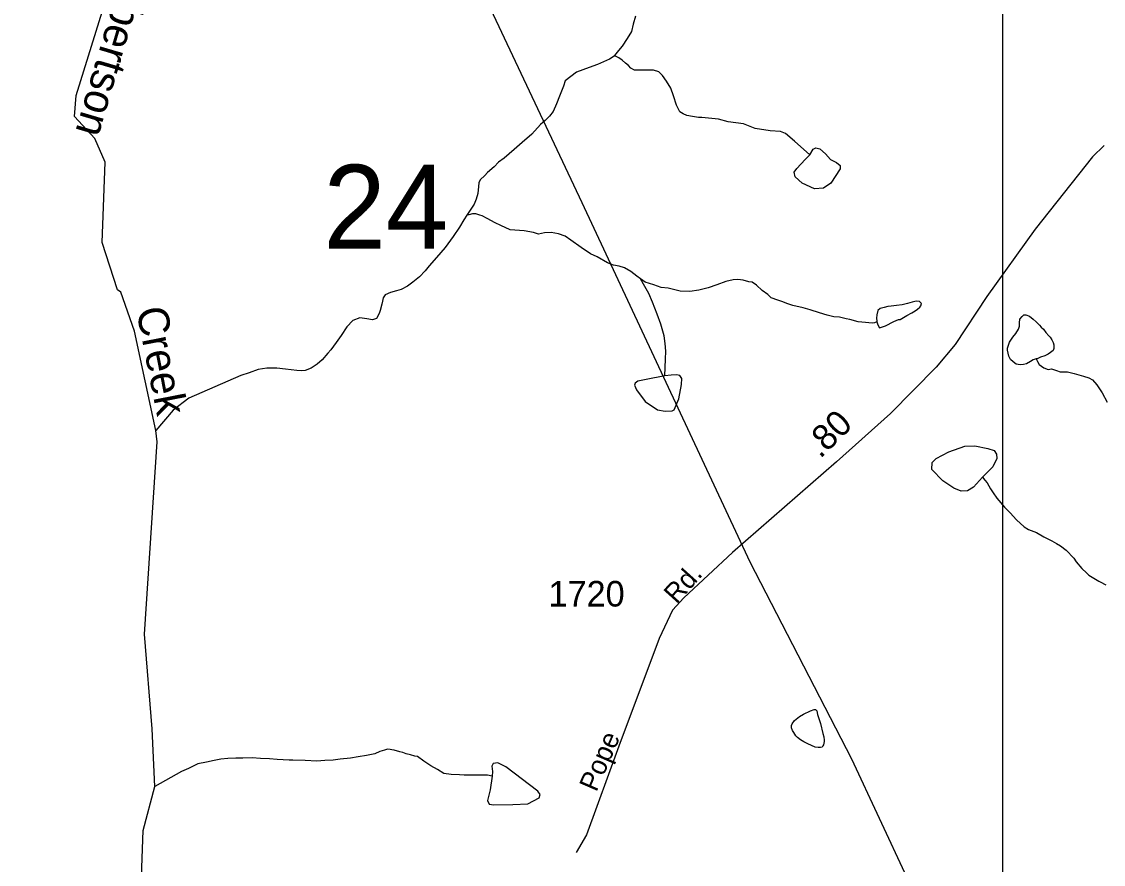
# Model space of a CAD drawing. Extents: x 2056842 to 2160602, y 826753 to 1016856.
# Drawn here: x 2099244 to 2104528, y 850429 to 854545 of the extents above; entities that cross this region are included whole.
import ezdxf

# ---------------------------------------------------------------- set-up
doc = ezdxf.new("R2010")
doc.units = 0
for name, color, linetype in [('Exist Hydrographic Creek Single Shore', 7, 'Continuous'), ('Exist Hydrographic Creek Single Shore Label', 7, 'Continuous'), ('Exist Hydrographic Misc Water Feature', 7, 'Continuous'), ('Exist Road Secondary Mileage Hundredths English Label', 7, 'Continuous'), ('Exist Road Secondary Structure Standard Bridge Number Label', 7, 'Continuous'), ('Exist Road Secondary Type 51 Attributed', 7, 'Continuous'), ('Exist Road Secondary Type 51 Label', 7, 'Continuous'), ('Exist Road Secondary Type 51 Number Label', 7, 'Continuous'), ('Exist Utilities Electrical Transmission Line', 7, 'Continuous'), ('Map Preparation Inset Cut Line', 7, 'Continuous')]:
    doc.layers.add(name, color=color, linetype=linetype)

msp = doc.modelspace()

# ---------------------------------------------------------------- linework, layer by layer
at = {"layer": 'Exist Hydrographic Creek Single Shore'}
for points in [[(2099906, 852492), (2099899, 852547.4), (2099796.1, 853032.3), (2099729, 853223.9), (2099713, 853234.1), (2099637.1, 853465.4), (2099652.1, 853858.8), (2099602.1, 853974.7), (2099502, 854081.7), (2099510, 854183.3), (2099683.1, 854740.8), (2099666.1, 854800.2), (2099483.4, 854923.4), (2099432.1, 854982.2), (2099429, 855060), (2099465.7, 855207), (2099537.5, 855293.5)], [(2102243.2, 854571.9), (2102231.5, 854531.9), (2102223.7, 854495.8), (2102201.5, 854461.8), (2102177.6, 854425.6), (2102159.9, 854403.6), (2102139.8, 854379.4), (2102137.8, 854375.7)], [(2102137.8, 854375.7), (2102115.8, 854361.6), (2102056.4, 854335.3), (2102016.2, 854321.1), (2101986, 854309), (2101954.3, 854298.8), (2101898.5, 854254.9), (2101890.3, 854229), (2101870.8, 854180.8), (2101856.9, 854142.8), (2101841.1, 854106.6), (2101823, 854082.5), (2101801.1, 854062.7), (2101778.9, 854042.5), (2101735.3, 853994.4), (2101689.5, 853954.3), (2101649.3, 853920.2), (2101601.6, 853877.9), (2101573.5, 853857.8), (2101551.5, 853836), (2101519.7, 853807.6), (2101506, 853793.8), (2101483.9, 853771.6), (2101477.7, 853757.5), (2101475.7, 853739.6), (2101472.2, 853705.6), (2101464, 853677.7), (2101454.1, 853653.6), (2101428.3, 853613.7), (2101418.2, 853599.4)], [(2101418.2, 853599.4), (2101404.5, 853577.5), (2101382.8, 853541.4), (2101352.4, 853495.3), (2101312.8, 853441.3), (2101271, 853393.2), (2101235.3, 853352.8), (2101215.2, 853327), (2101187.2, 853298.8), (2101155.2, 853272.8), (2101129.3, 853252.8), (2101097.3, 853236.5), (2101075.6, 853230.5), (2101045.7, 853222.5), (2101019.4, 853210.2), (2101009.6, 853196.3), (2101005.9, 853180.2), (2101003.8, 853164.3), (2100995.8, 853134.3), (2100990.1, 853120.1), (2100978, 853094.3), (2100957.9, 853088.1), (2100930, 853093.9), (2100896.2, 853097.8), (2100862.4, 853085.9), (2100832.4, 853053.5), (2100804.1, 853011.6), (2100780.1, 852977.5), (2100754.7, 852941.6), (2100740.5, 852925.5), (2100712.7, 852893.6), (2100686.8, 852871.1), (2100658.7, 852853), (2100628.8, 852841.3), (2100608.7, 852839.1), (2100588.6, 852840.9), (2100532.8, 852847), (2100490.8, 852852.9), (2100441, 852852.4), (2100398.9, 852846.6), (2100354.8, 852830.1), (2100314.7, 852816.3), (2100060.8, 852705.7), (2099984.9, 852647.4), (2099899, 852547.4)], [(2099396, 847840.1), (2099337.2, 848048), (2099358.4, 848423.4), (2099545.8, 848727.5), (2099647, 849140.5), (2099707.8, 849374.9), (2099781.3, 849638.4), (2099898, 849860.7), (2099939.8, 849955.3), (2099959.5, 850082), (2099939, 850174.8), (2099863.1, 850258.4), (2099830.1, 850367.4), (2099837.1, 850593.6), (2099895.1, 850809), (2099881.7, 851091.5), (2099843.7, 851552.7), (2099906, 852492)]]:
    msp.add_lwpolyline(points, dxfattribs=at)
at = {"layer": 'Exist Hydrographic Misc Water Feature'}
for points in [[(2103093.4, 853893.7), (2103018.7, 853960.8), (2102974.4, 853998.8), (2102950.3, 854007.7), (2102900.9, 854011.5), (2102827.5, 854022.9), (2102769.3, 854045.7), (2102694.6, 854055.8), (2102647.7, 854068.5), (2102566.5, 854077), (2102550.3, 854077), (2102520.4, 854080.7), (2102492.5, 854086.6), (2102474.7, 854094.6), (2102458.7, 854104.7), (2102442.7, 854136.8), (2102428.1, 854182.4), (2102414.6, 854220.5), (2102394.3, 854254.5), (2102374.2, 854282.2), (2102355.9, 854300.4), (2102330.1, 854308), (2102304.1, 854307.9), (2102273.9, 854308), (2102265.9, 854308), (2102237.8, 854307.8), (2102220.4, 854317.7), (2102207.9, 854329.8), (2102193.8, 854341.7), (2102178, 854355.8), (2102161.6, 854367.6), (2102147.6, 854373.8), (2102137.8, 854375.7)], [(2103093.4, 853893.7), (2103109.9, 853921.5), (2103122.5, 853929.1), (2103142.8, 853924.1), (2103170.6, 853898.7), (2103194.7, 853872.1), (2103223.8, 853856.9), (2103241.5, 853841.7), (2103241.5, 853826.5), (2103196, 853755.6), (2103160.5, 853731.5), (2103116.2, 853727.7), (2103056.7, 853755.6), (2103022.5, 853787.2), (2103017.4, 853808.8), (2103030.1, 853827.8), (2103071.9, 853870.9), (2103093.4, 853893.7)], [(2102267.4, 853288.1), (2102249.3, 853302.2), (2102219.4, 853323.8), (2102189.2, 853341.8), (2102163.2, 853349.7), (2102134.9, 853355.7), (2102105, 853367.5), (2102054.9, 853395.4), (2102023.1, 853411.5), (2101976.6, 853441.3), (2101926.6, 853476.9), (2101898.9, 853496.9), (2101866.9, 853509), (2101830.4, 853514.6), (2101798.6, 853512.5), (2101768.7, 853506.5), (2101744.5, 853514.6), (2101698.8, 853522.4), (2101630.9, 853528.2), (2101584.7, 853549.8), (2101556.5, 853561.8), (2101518.1, 853583.8), (2101494.1, 853595.6), (2101482.6, 853599.8), (2101462.3, 853605.7), (2101446.5, 853605.6), (2101428.5, 853601.5), (2101418.2, 853599.4)], [(2103421.8, 853077.9), (2103409.5, 853073.7), (2103397.8, 853071.8), (2103365.6, 853075.5), (2103329.3, 853079.3), (2103289.3, 853089.5), (2103271.3, 853093.4), (2103239.5, 853101), (2103211.8, 853103.2), (2103179.4, 853110.9), (2103141.5, 853122.8), (2103095.4, 853136.7), (2103061.3, 853146.7), (2103011.5, 853158.3), (2102981.4, 853168.6), (2102961.5, 853176.5), (2102937.3, 853184.2), (2102905.3, 853196.3), (2102889.1, 853212.2), (2102861.4, 853232.2), (2102833.1, 853258), (2102812.8, 853272), (2102795.4, 853273.9), (2102768.9, 853281.9), (2102742.9, 853285.8), (2102719.1, 853283.7), (2102683, 853275.4), (2102639.1, 853259.4), (2102597.1, 853245), (2102551.4, 853232.9), (2102507.5, 853227), (2102461.3, 853228.7), (2102401.3, 853242.7), (2102367.4, 853246.6), (2102331.3, 853258.5), (2102289.3, 853272.2), (2102267.4, 853288.1)], [(2102385, 852815.1), (2102388.3, 852896.5), (2102390.4, 852934.7), (2102388.1, 852972.4), (2102382.2, 853010.6), (2102366, 853066.6), (2102347.5, 853116.5), (2102325.8, 853174.2), (2102307.1, 853216.3), (2102281.3, 853262.1), (2102267.4, 853288.1)], [(2103421.8, 853077.9), (2103425.3, 853064), (2103434.1, 853049.7), (2103463.8, 853059.8), (2103503.6, 853080.1), (2103527.4, 853090.3), (2103535.6, 853090.3), (2103567.8, 853110.2), (2103591.6, 853122.4), (2103609.2, 853132.3), (2103619.1, 853140.5), (2103631.4, 853150.4), (2103635.5, 853156.3), (2103639.6, 853168.3), (2103635.1, 853172.6), (2103629.3, 853178.4), (2103613.5, 853180.3), (2103593.4, 853174.5), (2103571.1, 853168.1), (2103545.5, 853162.2), (2103517.6, 853157.9), (2103491.3, 853155.8), (2103475.1, 853153.8), (2103457.3, 853148), (2103437.4, 853143.7), (2103425.5, 853133.8), (2103421.8, 853113.6), (2103419.6, 853095.7), (2103421.6, 853081.6), (2103421.8, 853077.9)], [(2104200.2, 852898.3), (2104184.2, 852892.2), (2104172.3, 852884.3), (2104151.8, 852874), (2104138.1, 852870), (2104121.9, 852868), (2104102.2, 852871.7), (2104086.4, 852883.9), (2104074.1, 852893.9), (2104065.9, 852911.7), (2104059.9, 852939.8), (2104059.9, 852950), (2104069.6, 852979.8), (2104086, 853003.6), (2104099.5, 853021.8), (2104113.7, 853042), (2104117.6, 853058.1), (2104117.6, 853073.9), (2104119.8, 853091.9), (2104131.1, 853103.9), (2104139.3, 853112), (2104149.5, 853112.1), (2104167.6, 853106.1), (2104185.6, 853092), (2104199.4, 853078.1), (2104215.6, 853062.3), (2104223.6, 853052.2), (2104235.5, 853042.2), (2104247.3, 853026.3), (2104261.7, 853010.3), (2104267.9, 853004.5), (2104275.9, 852990.3), (2104281.8, 852978.4), (2104285.9, 852966.5), (2104285.9, 852956.3), (2104285.9, 852948.6), (2104282, 852938.6), (2104269.7, 852928.3), (2104258.2, 852920.3), (2104242, 852912.2), (2104220.1, 852906.2), (2104203.9, 852898.1), (2104200.2, 852898.3)], [(2104200.2, 852898.3), (2104206.3, 852884.4), (2104214.1, 852870.2), (2104236.1, 852854.3), (2104258.6, 852846.4), (2104273.8, 852848.6), (2104298.4, 852840.4), (2104316, 852834.5), (2104352.3, 852834.7), (2104384.5, 852826.9), (2104430.3, 852813.1), (2104456.1, 852805.2), (2104474.3, 852795.1), (2104496.3, 852771.1), (2104522.5, 852731.4), (2104546.7, 852685.5)], [(2102385, 852815.1), (2102295.1, 852797.4), (2102254.6, 852788.5), (2102240.6, 852779.7), (2102238.1, 852769.5), (2102247, 852746.7), (2102290, 852689.7), (2102349.5, 852649.2), (2102387.5, 852642.8), (2102421.7, 852644.1), (2102430.6, 852649.2), (2102454.6, 852702.4), (2102467.3, 852772.1), (2102468.5, 852801.2), (2102458.4, 852816.4), (2102442, 852820.2), (2102416.6, 852818.9), (2102385, 852815.1)], [(2103937.9, 852319.6), (2103893.4, 852270.9), (2103864.3, 852253.1), (2103832.6, 852251.9), (2103797.1, 852265.8), (2103744, 852302.5), (2103689.5, 852357), (2103690.8, 852391.2), (2103711, 852411.5), (2103773.1, 852444.4), (2103851.6, 852471), (2103899.7, 852473.6), (2103963, 852459.6), (2103994.7, 852449.5), (2104006.1, 852433), (2104007.3, 852411.5), (2103987.1, 852369.7), (2103937.9, 852319.6)], [(2103937.9, 852319.6), (2103948, 852305.5), (2103960.1, 852291.6), (2103976.3, 852263.6), (2103990, 852243.6), (2104008.1, 852217.7), (2104044.1, 852173.7), (2104072.2, 852145.9), (2104102.8, 852112.1), (2104140.3, 852078), (2104162.7, 852064), (2104200.4, 852050.3), (2104236.7, 852028.5), (2104276.7, 852008.6), (2104299, 851996.7), (2104319.1, 851984.8), (2104346.8, 851962.7), (2104383.1, 851924.8), (2104395.4, 851907.1), (2104423.3, 851873.2), (2104445.4, 851853.3), (2104457.5, 851841.3), (2104505.3, 851811.3), (2104511.3, 851809.2), (2104539.1, 851793.6)], [(2103145.8, 851117.3), (2103157.9, 851067.2), (2103162, 851051.2), (2103164.1, 851035.5), (2103163.9, 851029.4), (2103162, 851021.2), (2103160.4, 851013.3), (2103158.1, 851007.2), (2103154, 851001.3), (2103146.2, 850999.2), (2103134.3, 850999.4), (2103120.2, 851001.1), (2103084.1, 851017.2), (2103064, 851027), (2103047.8, 851036.8), (2103034.1, 851049), (2103025.6, 851056.8), (2103015.6, 851072.9), (2103010.1, 851082.7), (2103003.9, 851095), (2103003.9, 851106.8), (2103007.6, 851114.7), (2103019.7, 851130.8), (2103043.9, 851151.1), (2103063.8, 851163), (2103097.4, 851179), (2103115.5, 851185.2), (2103121.4, 851185.1), (2103127.8, 851179.3), (2103131.5, 851161.3), (2103145.8, 851117.3)], [(2101543.1, 850860.3), (2101519.1, 850864.3), (2101487.1, 850863.9), (2101466.8, 850864.1), (2101432.8, 850864), (2101405.1, 850863.8), (2101383, 850865.9), (2101342.8, 850867.5), (2101306.9, 850873.4), (2101274.9, 850891.6), (2101242.7, 850909.4), (2101208.9, 850933.2), (2101176.9, 850955.2), (2101164.8, 850957), (2101142.9, 850963.1), (2101122.6, 850969.1), (2101106.6, 850974.7), (2101090.6, 850978.8), (2101064.3, 850986.8), (2101052.8, 850988.5), (2101044.6, 850990.6), (2101030.5, 850990.7), (2101016.8, 850986.7), (2100994.4, 850980.3), (2100968.6, 850968.5), (2100928.6, 850960.3), (2100888.6, 850954.2), (2100850.5, 850948.2), (2100800.6, 850941.9), (2100766.4, 850937.8), (2100724.4, 850935.6), (2100686.6, 850933.6), (2100628.8, 850935.5), (2100569.1, 850937.3), (2100550.9, 850937.2), (2100492.8, 850941.1), (2100454.7, 850944.9), (2100410.8, 850946.6), (2100370.8, 850948.7), (2100324.9, 850948.3), (2100290.9, 850948.2), (2100251.1, 850946.1), (2100216.8, 850941.9), (2100184.9, 850936.3), (2100146.9, 850927.8), (2100104.7, 850920), (2100059, 850897.7), (2100025.3, 850881.7), (2099895.1, 850809)], [(2101543.1, 850860.3), (2101532.1, 850793.2), (2101519.4, 850741.2), (2101528.3, 850723.5), (2101549.8, 850719.7), (2101643.5, 850720.9), (2101717, 850724.7), (2101743.5, 850738.7), (2101772.7, 850753.9), (2101776.5, 850770.4), (2101765.1, 850785.6), (2101609.3, 850904.6), (2101570.1, 850924.9), (2101547.3, 850921.1), (2101541, 850908.4), (2101543.5, 850883.1), (2101543.1, 850860.3)]]:
    msp.add_lwpolyline(points, dxfattribs=at)
at = {"layer": 'Exist Road Secondary Type 51 Attributed'}
msp.add_lwpolyline([(2104531, 853939.9), (2104475.4, 853884.3), (2104195, 853532), (2103957.7, 853202.1), (2103804, 852968.2), (2103711.1, 852856.5), (2103487.8, 852631), (2103224.1, 852394.1), (2102716.8, 851951.9), (2102478.5, 851730.1), (2102423.4, 851670.8), (2102358, 851531.6), (2102161.2, 851006.3), (2102003.9, 850573.5), (2101953, 850487.2)], dxfattribs=at)
at = {"layer": 'Exist Utilities Electrical Transmission Line'}
msp.add_lwpolyline([(2090208.9, 878090.6), (2090399.6, 877911.2), (2091042.2, 877021.2), (2091166.6, 876875.7), (2095091.8, 871822.6), (2095202.4, 871658.9), (2098164.4, 867008.7), (2098184.9, 866904.8), (2098734, 864623.2), (2099022.7, 863475.6), (2099626.1, 861080), (2100400.4, 858056.5), (2100951.6, 855844.8), (2101980.8, 853661.7), (2102801.4, 851906.3), (2103296.8, 850944.6), (2103702.1, 850075), (2103840.6, 849731.1), (2105377.5, 846510.3), (2106244.1, 844636.9), (2107548.3, 841869.9), (2108761.2, 839864.8), (2109358.7, 838871.2), (2109834.3, 838086.5)], dxfattribs=at)
at = {"layer": 'Map Preparation Inset Cut Line'}
msp.add_lwpolyline([(2059276.8, 845851.8), (2104036.2, 845851.8), (2104036.2, 868310.8), (2085975.1, 868308.6), (2085982, 877260.1), (2059276.8, 877260.1), (2059276.8, 845851.8)], dxfattribs=at)

# ---------------------------------------------------------------- texts
at = {"layer": 'Exist Hydrographic Creek Single Shore Label'}
for s, rotation, p in [('Robertson', 253.5974, (2099767.4, 854897.1)), ('Creek', 281.0826, (2099803.3, 853138.4))]:
    msp.add_text(s, height=150, rotation=rotation, dxfattribs=at).set_placement(p)
at = {"layer": 'Exist Road Secondary Mileage Hundredths English Label'}
msp.add_text('.80', height=125, rotation=44.5433, dxfattribs=at).set_placement((2103144.3, 852407.5))
at = {"layer": 'Exist Road Secondary Structure Standard Bridge Number Label'}
msp.add_text('24', height=410.1, dxfattribs=at).set_placement((2100718, 853435.5))
at = {"layer": 'Exist Road Secondary Type 51 Label'}
for s, rotation, p in [('Rd.', 48.0169, (2102442.7, 851696.8)), ('Pope', 66.5786, (2102051.3, 850778.6))]:
    msp.add_text(s, height=95, rotation=rotation, dxfattribs=at).set_placement(p)
at = {"layer": 'Exist Road Secondary Type 51 Number Label'}
msp.add_text('1720', height=125, dxfattribs=at).set_placement((2101817.7, 851688.2))

doc.saveas('drawing.dxf')
